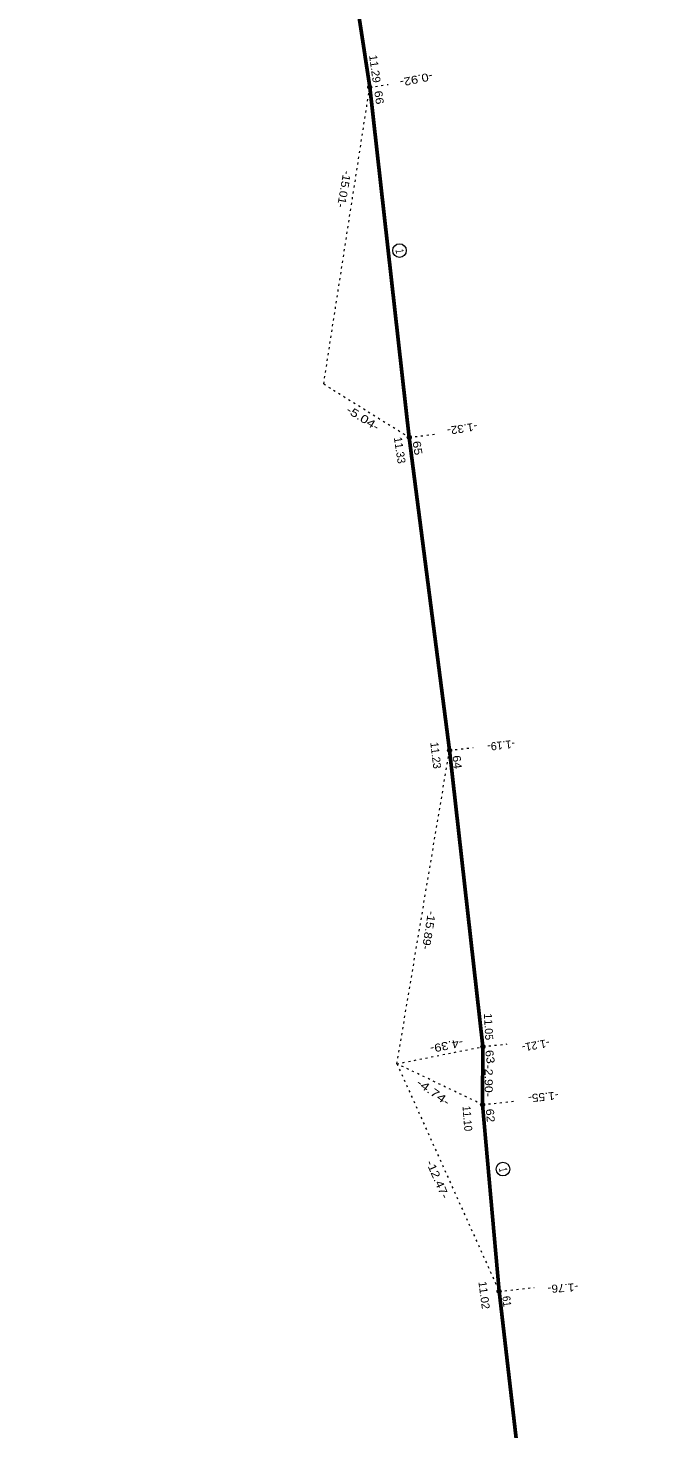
# Model space of a CAD drawing. Extents: x -603113 to -602961, y -1157278 to -1156712.
# Drawn here: x -603008.1 to -602976.9, y -1156987.2 to -1156917.2 of the extents above; entities that cross this region are included whole.
import ezdxf
from ezdxf.enums import TextEntityAlignment as Align

# ---------------------------------------------------------------- set-up
doc = ezdxf.new("R2010")
doc.units = 0
doc.header["$LTSCALE"] = 0.16
doc.header["$PDMODE"] = 32
doc.header["$PDSIZE"] = 0.08
doc.linetypes.add('DOTTED', pattern=[1.5, 0.3, -1.2])
for name, color, linetype, lineweight in [('12', 7, 'Continuous', 53), ('14', 7, 'DOTTED', 13), ('15', 7, 'Continuous', 13)]:
    doc.layers.add(name, color=color, linetype=linetype, lineweight=lineweight)
doc.layers.add('35', color=7, linetype='Continuous')

msp = doc.modelspace()

# ---------------------------------------------------------------- linework, layer by layer
at = {"layer": '12'}
msp.add_lwpolyline([(-603008.05, -1156862.95), (-602999.4, -1156882.19), (-602997.95, -1156885.06), (-602993.7, -1156902.35), (-602990.97, -1156920.18), (-602988.99, -1156937.68), (-602986.98, -1156953.32), (-602985.31, -1156968.13), (-602985.33, -1156971.03), (-602984.5, -1156980.36), (-602982.87, -1156994.49), (-602980.87, -1157012.29), (-602979.02, -1157028.94), (-602976.91, -1157038.635)], dxfattribs=at)
at = {"layer": '14'}
for p, q in [((-602993.27, -1156935.01), (-602990.97, -1156920.18)), ((-602990.97, -1156920.18), (-602990.055, -1156920.046)), ((-602993.27, -1156935.01), (-602988.99, -1156937.68)), ((-602988.99, -1156937.68), (-602987.683, -1156937.52)), ((-602986.98, -1156953.32), (-602985.793, -1156953.183)), ((-602985.31, -1156968.13), (-602984.106, -1156967.996)), ((-602989.61, -1156968.99), (-602985.31, -1156968.13)), ((-602989.61, -1156968.99), (-602984.5, -1156980.36)), ((-602985.33, -1156971.03), (-602983.788, -1156970.859)), ((-602984.5, -1156980.36), (-602982.752, -1156980.164))]:
    msp.add_line(p, q, dxfattribs=at)
msp.add_lwpolyline([(-602985.33, -1156971.03), (-602989.61, -1156968.99), (-602986.98, -1156953.32)], dxfattribs=at)
at = {"layer": '15'}
for centre, radius in [((-602990.97, -1156920.18), 0.1), ((-602989.4809, -1156928.3434), 0.3414), ((-602988.99, -1156937.68), 0.1), ((-602986.98, -1156953.32), 0.1), ((-602985.31, -1156968.13), 0.1), ((-602985.33, -1156971.03), 0.1), ((-602984.3089, -1156974.2484), 0.3414), ((-602984.5, -1156980.36), 0.1)]:
    msp.add_circle(centre, radius, dxfattribs=at)
for p in [(-602990.97, -1156920.18), (-602988.99, -1156937.68), (-602986.98, -1156953.32), (-602985.31, -1156968.13), (-602985.33, -1156971.03), (-602984.5, -1156980.36)]:
    msp.add_point(p, dxfattribs=at)

# ---------------------------------------------------------------- texts
at = {"layer": '14'}
for s, rotation, width, p in [('-0.92-', 191.648, 1.2, (-602987.862, -1156919.426)), ('-15.01-', 260.061, 1.1, (-602992.281, -1156924.329)), ('-5.04-', 327.918, 1.3, (-602992.186, -1156936.405)), ('-1.32-', 188.662, 1.1, (-602985.614, -1156936.933)), ('-15.89-', 260.73, 1.15, (-602988.051, -1156961.327)), ('-4.39-', 191.816, 1.2, (-602986.345, -1156967.719)), ('-2.90-', 270, 1.15, (-602985.22, -1156969.032)), ('-4.74-', 324.481, 1.35, (-602988.674, -1156970.015)), ('-1.55-', 185.597, 1.1, (-602981.544, -1156970.37)), ('-12.47-', 293.69, 1.2, (-602988.163, -1156973.908)), ('-1.76-', 183.797, 1.1, (-602980.559, -1156979.947))]:
    msp.add_text(s, height=0.4, rotation=rotation, dxfattribs=dict(at, width=width)).set_placement(p)
for s, rotation, p in [('-1.19-', 186.375, (-602983.727, -1156952.797)), ('-1.21-', 190.149, (-602982.017, -1156967.745))]:
    msp.add_text(s, height=0.4, rotation=rotation, dxfattribs=at).set_placement(p)
at = {"layer": '15'}
for s, rotation, width, p in [('66', 277.855, 1.15, (-602990.743, -1156920.382)), ('1', 279.483, 0.65, (-602989.681, -1156928.308)), ('65', 278.838, 1.2, (-602988.829, -1156937.89)), ('64', 276.367, 1.15, (-602986.83, -1156953.591)), ('63', 277.557, 1.15, (-602985.2, -1156968.325)), ('62', 275.025, 1.15, (-602985.168, -1156971.254)), ('1', 279.483, 0.65, (-602984.509, -1156974.213)), ('61', 276.598, 0.9, (-602984.344, -1156980.615))]:
    msp.add_text(s, height=0.4, rotation=rotation, dxfattribs=dict(at, width=width)).set_placement(p)
at = {"layer": '35'}
for s, rotation, width, p in [('11.29', 277.838, 1.05, (-602990.9071, -1156919.2857)), ('11.10', 274.358, 0.95, (-602986.2831, -1156971.7378)), ('11.02', 277.508, 1.05, (-602985.4463, -1156980.5804))]:
    msp.add_text(s, height=0.4, rotation=rotation, dxfattribs=dict(at, width=width)).set_placement(p, align=Align.CENTER)
for s, rotation, p in [('11.33', 278.638, (-602989.6647, -1156938.3535)), ('11.23', 276.822, (-602987.864, -1156953.5962)), ('11.05', 272.89, (-602985.226, -1156967.1474))]:
    msp.add_text(s, height=0.4, rotation=rotation, dxfattribs=at).set_placement(p, align=Align.CENTER)

doc.saveas('drawing.dxf')
